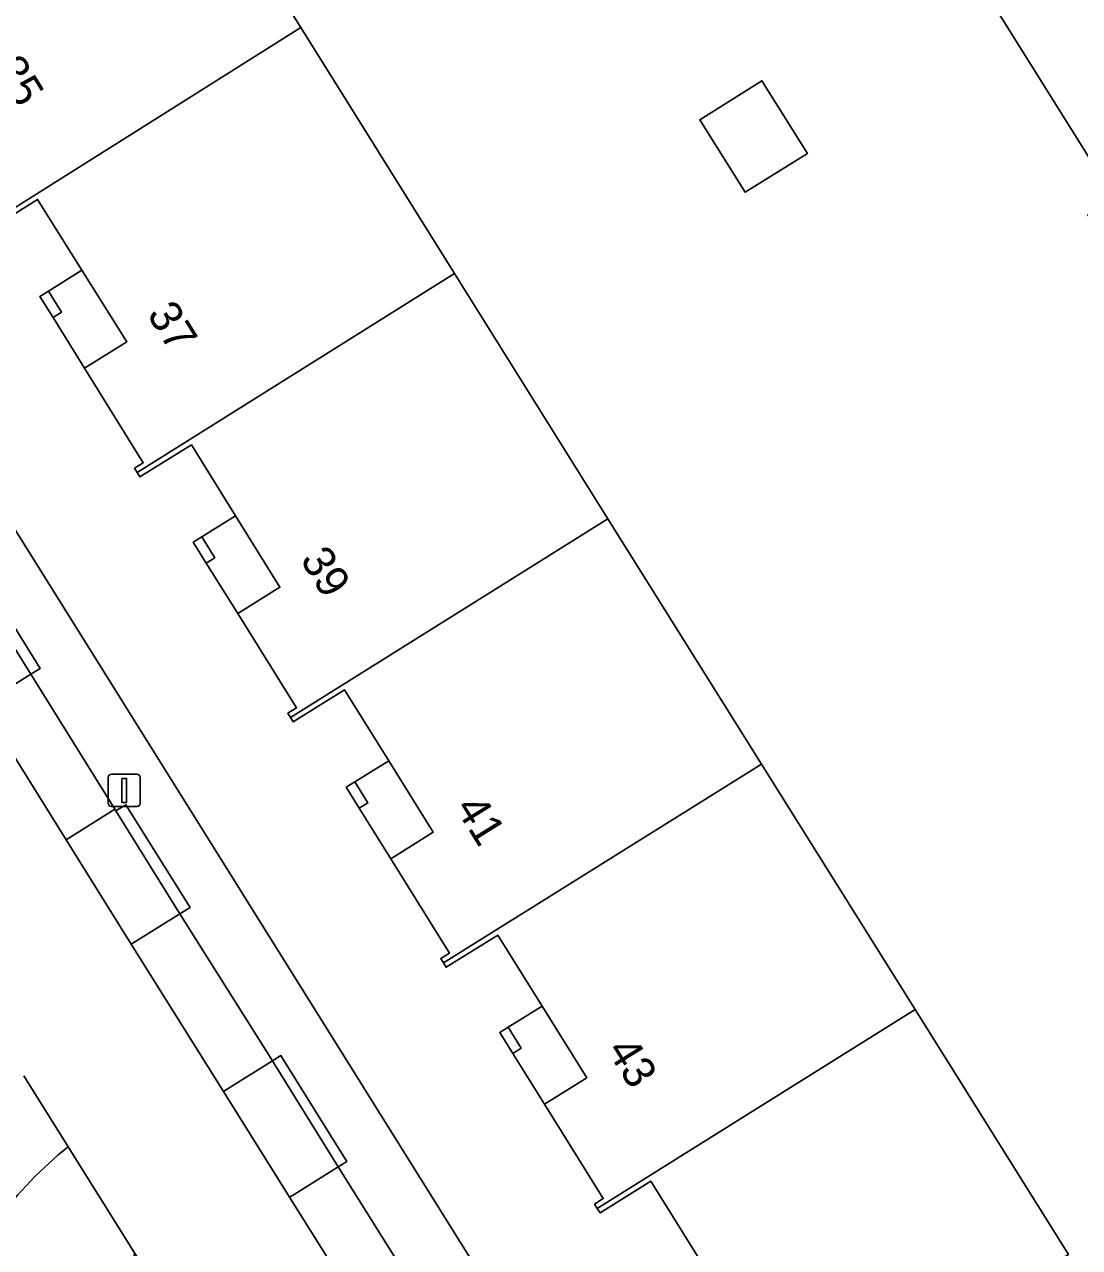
# Model space of a CAD drawing. Extents: x 158835 to 160077, y 386387 to 387778.
# Drawn here: x 159192.87 to 159225.67, y 387026.31 to 387064.34 of the extents above; entities that cross this region are included whole.
import ezdxf

# ---------------------------------------------------------------- set-up
doc = ezdxf.new("R2010")
doc.units = 0
for name, color, linetype in [('IMGEO_Erf', 7, 'Continuous'), ('IMGEO_Groenvoorziening', 7, 'Continuous'), ('IMGEO_Lichtmast', 7, 'Continuous'), ('IMGEO_Pand', 7, 'Continuous'), ('IMGEO_Pand_nummerreeks', 7, 'Continuous'), ('IMGEO_Pand_overbouw', 7, 'Continuous'), ('IMGEO_Parkeervlak_open', 7, 'Continuous'), ('IMGEO_Rijbaan_lokaal_open', 7, 'Continuous'), ('IMGEO_Voetpad_halfverhard', 7, 'Continuous'), ('IMGEO_Voetpad_open', 7, 'Continuous')]:
    doc.layers.add(name, color=color, linetype=linetype)

msp = doc.modelspace()

# ---------------------------------------------------------------- linework, layer by layer
at = {"layer": 'IMGEO_Erf'}
for points in [[(159158.165, 387103.724), (159222.278, 387001.075)], [(159191.861, 387079.631), (159194.412, 387081.226), (159194.581, 387080.955), (159194.293, 387080.775), (159196.869, 387076.656), (159194.589, 387075.23), (159196.693, 387071.865), (159201.459, 387064.245), (159206.24, 387056.6), (159211.01, 387048.972), (159215.782, 387041.343), (159220.557, 387033.707), (159225.323, 387026.087)], [(159226.754, 387058.936), (159222.155, 387066.296)], [(159213.712, 387026.172), (159212.342, 387028.371), (159210.763, 387027.387), (159210.678, 387027.523), (159210.593, 387027.658), (159210.865, 387027.828), (159209.034, 387030.766), (159210.349, 387031.585), (159208.959, 387033.818), (159207.584, 387036.026), (159205.979, 387035.026), (159205.895, 387035.16), (159205.81, 387035.297), (159206.081, 387035.466), (159204.256, 387038.399), (159205.577, 387039.221), (159204.193, 387041.445), (159202.823, 387043.647), (159201.223, 387042.651), (159201.139, 387042.786), (159201.054, 387042.922), (159201.325, 387043.09), (159199.5, 387046.023), (159200.813, 387046.84), (159199.429, 387049.064), (159198.059, 387051.266), (159196.458, 387050.27), (159196.374, 387050.406), (159196.289, 387050.542), (159196.561, 387050.711), (159194.738, 387053.65), (159196.052, 387054.474), (159194.656, 387056.703), (159193.279, 387058.901), (159191.696, 387057.909)]]:
    msp.add_lwpolyline(points, dxfattribs=at)
for points in [[(159217.209, 387060.33), (159215.277, 387059.122), (159213.865, 387061.381), (159215.797, 387062.589)], [(159194.02, 387055.394), (159193.757, 387055.231), (159193.351, 387055.885), (159193.614, 387056.05)], [(159198.786, 387047.757), (159198.523, 387047.593), (159198.116, 387048.247), (159198.379, 387048.411)], [(159203.542, 387040.133), (159203.279, 387039.969), (159202.872, 387040.623), (159203.135, 387040.787)], [(159208.313, 387032.508), (159208.05, 387032.345), (159207.643, 387032.998), (159207.906, 387033.162)]]:
    msp.add_lwpolyline(points, close=True, dxfattribs=at)
at = {"layer": 'IMGEO_Groenvoorziening'}
msp.add_lwpolyline([(159195.504, 387022.588), (159195.882, 387023.745), (159196.144, 387024.932), (159196.288, 387026.14), (159194.224, 387029.442)], dxfattribs=at)
msp.add_arc((159202.972, 387018.745), 13.819, 129.2772, 155.5065, dxfattribs=at)
at = {"layer": 'IMGEO_Lichtmast'}
for p, q in [((159195.575, 387041.023), (159196.365, 387041.023)), ((159196.365, 387041.023), (159195.575, 387041.023)), ((159195.475, 387040.123), (159195.475, 387040.923)), ((159195.475, 387040.923), (159195.475, 387040.123)), ((159196.465, 387040.923), (159196.465, 387040.123)), ((159196.465, 387040.123), (159196.465, 387040.923)), ((159196.365, 387040.023), (159195.575, 387040.023)), ((159195.575, 387040.023), (159196.365, 387040.023))]:
    msp.add_line(p, q, dxfattribs=at)
msp.add_lwpolyline([(159195.895, 387040.898), (159196.045, 387040.898), (159196.045, 387040.148), (159195.895, 387040.148), (159195.895, 387040.898)], dxfattribs=at)
for centre, start, end in [((159195.575, 387040.923), 90, 180), ((159195.575, 387040.923), 90, 180), ((159196.365, 387040.923), 0, 90), ((159196.365, 387040.923), 360, 90), ((159195.575, 387040.123), 180, 270), ((159195.575, 387040.123), 180, 270), ((159196.365, 387040.123), 270, 0), ((159196.365, 387040.123), 270, 0)]:
    msp.add_arc(centre, 0.1, start, end, dxfattribs=at)
at = {"layer": 'IMGEO_Pand'}
for points in [[(159234.24, 387067.673), (159232.92, 387066.848), (159231.509, 387069.082), (159230.151, 387071.292), (159232.302, 387072.614), (159232.217, 387072.75), (159221.79, 387066.257), (159221.875, 387066.121), (159222.155, 387066.296), (159226.754, 387058.936), (159225.932, 387058.422), (159226.016, 387058.286), (159236.446, 387064.776), (159236.361, 387064.912), (159236.08, 387064.736)], [(159196.693, 387071.865), (159186.843, 387065.678), (159186.927, 387065.543), (159188.521, 387066.546), (159189.896, 387064.362), (159191.297, 387062.136), (159189.968, 387061.3), (159191.799, 387058.351), (159191.527, 387058.181), (159191.612, 387058.044), (159201.459, 387064.245)], [(159201.459, 387064.245), (159191.612, 387058.044), (159191.696, 387057.909), (159193.279, 387058.901), (159194.656, 387056.703), (159196.052, 387054.474), (159194.738, 387053.65), (159196.561, 387050.711), (159196.289, 387050.542), (159196.374, 387050.406), (159206.24, 387056.6)], [(159213.865, 387061.381), (159215.277, 387059.122), (159217.209, 387060.33), (159215.797, 387062.589)], [(159206.24, 387056.6), (159196.374, 387050.406), (159196.458, 387050.27), (159198.059, 387051.266), (159199.429, 387049.064), (159200.813, 387046.84), (159199.5, 387046.023), (159201.325, 387043.09), (159201.054, 387042.922), (159201.139, 387042.786), (159211.01, 387048.972)], [(159193.614, 387056.05), (159193.351, 387055.885), (159193.757, 387055.231), (159194.02, 387055.394)], [(159211.01, 387048.972), (159201.139, 387042.786), (159201.223, 387042.651), (159202.823, 387043.647), (159204.193, 387041.445), (159205.577, 387039.221), (159204.256, 387038.399), (159206.081, 387035.466), (159205.81, 387035.297), (159205.895, 387035.16), (159215.782, 387041.343)], [(159198.379, 387048.411), (159198.116, 387048.247), (159198.523, 387047.593), (159198.786, 387047.757)], [(159215.782, 387041.343), (159205.895, 387035.16), (159205.979, 387035.026), (159207.584, 387036.026), (159208.959, 387033.818), (159210.349, 387031.585), (159209.034, 387030.766), (159210.865, 387027.828), (159210.593, 387027.658), (159210.678, 387027.523), (159220.557, 387033.707)], [(159203.135, 387040.787), (159202.872, 387040.623), (159203.279, 387039.969), (159203.542, 387040.133)], [(159220.557, 387033.707), (159210.678, 387027.523), (159210.763, 387027.387), (159212.342, 387028.371), (159213.712, 387026.172), (159215.097, 387023.948), (159213.79, 387023.133), (159215.626, 387020.186), (159215.355, 387020.017), (159215.44, 387019.88), (159225.323, 387026.087)], [(159207.906, 387033.162), (159207.643, 387032.998), (159208.05, 387032.345), (159208.313, 387032.508)]]:
    msp.add_lwpolyline(points, close=True, dxfattribs=at)
at = {"layer": 'IMGEO_Pand_overbouw'}
for points in [[(159194.738, 387053.65), (159196.052, 387054.474), (159194.656, 387056.703), (159193.614, 387056.05), (159193.351, 387055.885), (159193.757, 387055.231)], [(159199.5, 387046.023), (159200.813, 387046.84), (159199.429, 387049.064), (159198.379, 387048.411), (159198.116, 387048.247), (159198.523, 387047.593)], [(159204.256, 387038.399), (159205.577, 387039.221), (159204.193, 387041.445), (159203.135, 387040.787), (159202.872, 387040.623), (159203.279, 387039.969)], [(159209.034, 387030.766), (159210.349, 387031.585), (159208.959, 387033.818), (159207.906, 387033.162), (159207.643, 387032.998), (159208.05, 387032.345)]]:
    msp.add_lwpolyline(points, close=True, dxfattribs=at)
at = {"layer": 'IMGEO_Parkeervlak_open'}
for points in [[(159193.064, 387044.134), (159191.54, 387043.182), (159194.161, 387038.99), (159195.68, 387039.939)], [(159197.699, 387036.685), (159196.191, 387035.742), (159199.054, 387031.161), (159199.199, 387031.251), (159200.579, 387032.113)], [(159202.626, 387028.817), (159201.255, 387027.96), (159201.111, 387027.871), (159202.431, 387025.759), (159203.762, 387023.624), (159205.281, 387024.571)]]:
    msp.add_lwpolyline(points, close=True, dxfattribs=at)
at = {"layer": 'IMGEO_Rijbaan_lokaal_open'}
msp.add_lwpolyline([(159192.849, 387031.651), (159194.224, 387029.442), (159196.288, 387026.14), (159197.851, 387023.611), (159209.765, 387004.567), (159212.616, 387000), (159214.636, 386996.763), (159218.846, 386999.479), (159218.605, 386999.859), (159218.523, 387000), (159215.329, 387005.089), (159214.333, 387006.675), (159213.326, 387008.29), (159210.412, 387012.962), (159208.411, 387016.17), (159205.753, 387020.432), (159203.762, 387023.624), (159202.431, 387025.759), (159201.111, 387027.871), (159199.054, 387031.161), (159196.191, 387035.742), (159194.161, 387038.99), (159191.54, 387043.182)], dxfattribs=at)
at = {"layer": 'IMGEO_Voetpad_halfverhard'}
msp.add_lwpolyline([(159194.224, 387029.442), (159192.849, 387031.651)], dxfattribs=at)
msp.add_arc((159202.972, 387018.745), 13.819, 129.2772, 155.5065, dxfattribs=at)
at = {"layer": 'IMGEO_Voetpad_open'}
for points in [[(159218.523, 387000), (159218.605, 386999.859), (159218.846, 386999.479), (159219.137, 386999.039), (159219.467, 386998.628), (159219.832, 386998.247), (159220.23, 386997.901), (159224.402, 387000.372), (159224.237, 387000.328), (159224.069, 387000.298), (159223.899, 387000.284), (159223.728, 387000.285), (159223.558, 387000.302), (159223.391, 387000.333), (159223.226, 387000.38), (159223.067, 387000.44), (159222.913, 387000.515), (159222.767, 387000.603), (159222.63, 387000.704), (159222.501, 387000.817), (159222.384, 387000.941), (159222.278, 387001.075), (159158.165, 387103.724)], [(159191.365, 387047.518), (159193.358, 387044.317), (159193.064, 387044.134), (159195.68, 387039.939), (159195.715, 387039.883), (159196.025, 387040.075), (159198.019, 387036.883), (159197.699, 387036.685), (159200.579, 387032.113), (159200.84, 387032.276), (159200.905, 387032.172), (159202.896, 387028.985), (159202.626, 387028.817), (159205.281, 387024.571)]]:
    msp.add_lwpolyline(points, dxfattribs=at)
for points in [[(159191.365, 387047.518), (159191.072, 387047.336), (159193.064, 387044.134), (159193.358, 387044.317)], [(159191.072, 387047.336), (159189.551, 387046.417), (159190.51, 387044.83), (159191.54, 387043.182), (159193.064, 387044.134)], [(159195.715, 387039.883), (159195.68, 387039.939), (159194.161, 387038.99), (159196.191, 387035.742), (159197.699, 387036.685)], [(159196.025, 387040.075), (159195.715, 387039.883), (159197.699, 387036.685), (159198.019, 387036.883)], [(159200.84, 387032.276), (159200.579, 387032.113), (159200.644, 387032.01), (159202.626, 387028.817), (159202.896, 387028.985), (159200.905, 387032.172)], [(159200.644, 387032.01), (159200.579, 387032.113), (159199.199, 387031.251), (159199.054, 387031.161), (159201.111, 387027.871), (159201.255, 387027.96), (159202.626, 387028.817)]]:
    msp.add_lwpolyline(points, close=True, dxfattribs=at)

# ---------------------------------------------------------------- texts
at = {"layer": 'IMGEO_Pand_nummerreeks'}
for s, rotation, p in [('35', 301.8448, (159191.895, 387062.975)), ('37', 301.8161, (159196.662, 387055.329)), ('39', 301.8906, (159201.423, 387047.701)), ('41', 301.8906, (159206.239, 387039.981)), ('43', 301.9307, (159210.955, 387032.448))]:
    msp.add_text(s, height=1, rotation=rotation, dxfattribs=at).set_placement(p)

doc.saveas('drawing.dxf')
